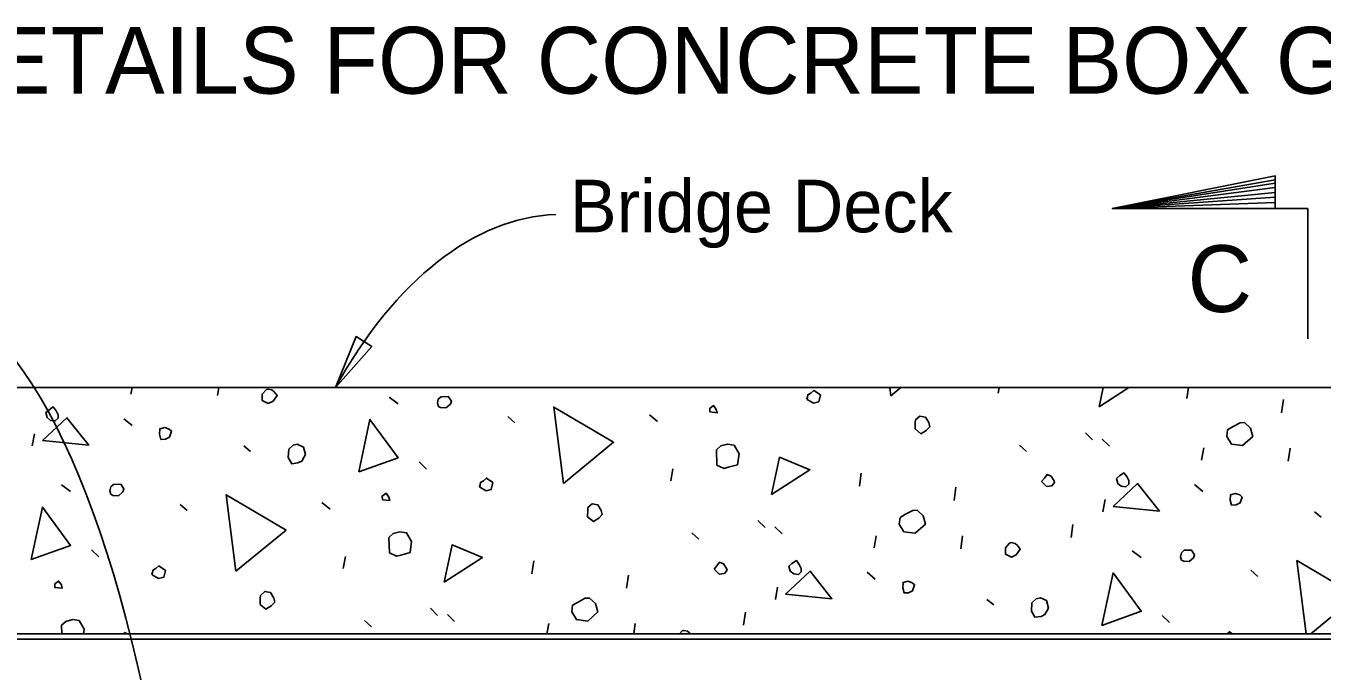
# Model space of a CAD drawing. Extents: x 112544 to 112597.1, y 111084 to 111107.1.
# Drawn here: x 112548.485 to 112552.213, y 111093.624 to 111095.48 of the extents above; entities that cross this region are included whole.
import ezdxf

# ---------------------------------------------------------------- set-up
doc = ezdxf.new("R2010")
doc.units = 0
for name, color, linetype in [('Dimension', 7, 'Continuous'), ('Miscellaneous', 7, 'Continuous'), ('SupstrConc', 7, 'Continuous'), ('TextStructures', 7, 'Continuous')]:
    doc.layers.add(name, color=color, linetype=linetype)

msp = doc.modelspace()

# ---------------------------------------------------------------- linework, layer by layer
at = {"layer": 'Dimension'}
for p, q in [((112551.609, 111094.9545), (112552.0777, 111095.037)), ((112552.0777, 111095.027), (112551.609, 111094.9545)), ((112551.609, 111094.9545), (112552.0777, 111095.0145)), ((112552.0777, 111095.0008), (112551.609, 111094.9545)), ((112551.609, 111094.9545), (112552.0777, 111094.987)), ((112552.0777, 111094.972), (112551.609, 111094.9545))]:
    msp.add_line(p, q, dxfattribs=at)
msp.add_lwpolyline([(112552.1714, 111094.5795), (112552.1714, 111094.9545), (112551.609, 111094.9545), (112552.0777, 111095.0483), (112552.0777, 111094.9545)], dxfattribs=at)
msp.add_lwpolyline([(112549.3749, 111094.4391), (112549.4796, 111094.558), (112549.4346, 111094.5859)], close=True, dxfattribs=at)
for centre, major_axis, ratio, start_param, end_param in [((112550.1201, 111092.5703), (0.1111, -2.3674), 0.464296, 3.141604, 3.781059), ((112548.1769, 111092.198), (0.0332, -2.5173), 0.313255, 2.075166, 3.141607)]:
    msp.add_ellipse(centre, major_axis=major_axis, ratio=ratio, start_param=start_param, end_param=end_param, dxfattribs=at)
at = {"layer": 'Miscellaneous'}
for p, q in [((112548.787, 111094.42), (112548.7903, 111094.4392)), ((112549.0363, 111094.4169), (112549.0395, 111094.4392)), ((112551.2812, 111094.4231), (112551.2839, 111094.4392)), ((112551.8236, 111094.408), (112551.8281, 111094.4392)), ((112549.5294, 111094.4118), (112549.5552, 111094.3929)), ((112552.0959, 111094.3671), (112552.1014, 111094.4048)), ((112548.7669, 111094.3499), (112548.7903, 111094.3303)), ((112549.8705, 111094.3557), (112549.8908, 111094.3379)), ((112550.278, 111094.3613), (112550.3013, 111094.3417)), ((112548.5032, 111094.2715), (112548.5093, 111094.3067)), ((112551.5317, 111094.3091), (112551.5527, 111094.2888)), ((112549.1115, 111094.2714), (112549.1312, 111094.2559)), ((112551.3419, 111094.2737), (112551.3622, 111094.2559)), ((112551.5805, 111094.2911), (112551.6015, 111094.2708)), ((112551.866, 111094.2304), (112551.872, 111094.2657)), ((112552.1153, 111094.2273), (112552.1207, 111094.265)), ((112549.6156, 111094.2253), (112549.6366, 111094.205)), ((112550.3394, 111094.1707), (112550.3455, 111094.206)), ((112550.8818, 111094.1556), (112550.8872, 111094.1933)), ((112548.5876, 111094.1595), (112548.6134, 111094.1405)), ((112551.8459, 111094.1603), (112551.8693, 111094.1407)), ((112551.1541, 111094.1147), (112551.1596, 111094.1524)), ((112551.5822, 111094.0819), (112551.5883, 111094.1172)), ((112548.9288, 111094.1034), (112548.9491, 111094.0855)), ((112549.3362, 111094.109), (112549.3596, 111094.0894)), ((112552.1905, 111094.0818), (112552.2101, 111094.0664)), ((112550.5899, 111094.0567), (112550.6109, 111094.0364)), ((112551.4907, 111094.0082), (112551.4961, 111094.0459)), ((112550.4001, 111094.0214), (112550.4204, 111094.0035)), ((112550.6387, 111094.0387), (112550.6597, 111094.0185)), ((112550.9242, 111093.978), (112550.9303, 111094.0133)), ((112551.1735, 111093.975), (112551.1789, 111094.0126)), ((112548.6738, 111093.9729), (112548.6948, 111093.9527)), ((112551.6666, 111093.9699), (112551.6924, 111093.9509)), ((112549.3976, 111093.9184), (112549.4037, 111093.9537)), ((112549.94, 111093.9033), (112549.9454, 111093.941)), ((112550.2124, 111093.8624), (112550.2178, 111093.9001)), ((112550.9041, 111093.908), (112550.9275, 111093.8883)), ((112552.0077, 111093.9138), (112552.028, 111093.8959)), ((112550.6404, 111093.8295), (112550.6465, 111093.8648)), ((112551.2487, 111093.8295), (112551.2684, 111093.814)), ((112549.6482, 111093.8044), (112549.6691, 111093.7841)), ((112549.697, 111093.7864), (112549.7179, 111093.7661)), ((112550.5489, 111093.7558), (112550.5543, 111093.7935)), ((112551.7528, 111093.7834), (112551.7738, 111093.7631)), ((112549.4583, 111093.769), (112549.4786, 111093.7512)), ((112549.9833, 111093.7309), (112549.9885, 111093.761)), ((112550.2329, 111093.7309), (112550.2371, 111093.7603)), ((112547.9235, 111093.7309), (112552.7436, 111093.7309)), ((112547.9277, 111093.7153), (112552.7436, 111093.7153))]:
    msp.add_line(p, q, dxfattribs=at)
for points in [[(112549.1648, 111094.4202), (112549.1645, 111094.402), (112549.1822, 111094.3939), (112549.196, 111094.4002), (112549.2073, 111094.4161), (112549.1992, 111094.4269), (112549.1925, 111094.4328), (112549.1815, 111094.4351), (112549.1767, 111094.4338), (112549.1648, 111094.4202)], [(112550.732, 111094.4054), (112550.7504, 111094.3948), (112550.7649, 111094.3986), (112550.77, 111094.4181), (112550.751, 111094.4312), (112550.7426, 111094.4237), (112550.7336, 111094.4187), (112550.732, 111094.4054), (112550.7307, 111094.4102)], [(112550.9726, 111094.4155), (112550.9696, 111094.4392)], [(112551.0014, 111094.4392), (112550.9726, 111094.4155)], [(112551.5711, 111094.3843), (112551.5829, 111094.4392)], [(112551.6564, 111094.4392), (112551.5711, 111094.3843)], [(112548.5461, 111094.3528), (112548.556, 111094.3451), (112548.5694, 111094.3435), (112548.5777, 111094.3509), (112548.5775, 111094.3612), (112548.5719, 111094.3727), (112548.5638, 111094.3835), (112548.5506, 111094.3747), (112548.5423, 111094.3673), (112548.5461, 111094.3528)], [(112549.6711, 111094.3851), (112549.6773, 111094.3816), (112549.693, 111094.3806), (112549.7056, 111094.3917), (112549.7085, 111094.4003), (112549.6998, 111094.4135), (112549.6792, 111094.4131), (112549.6708, 111094.4057), (112549.6685, 111094.3948), (112549.6711, 111094.3851)], [(112550.0308, 111094.1631), (112550.0029, 111094.3834), (112550.175, 111094.282), (112550.0308, 111094.1631)], [(112550.4519, 111094.3691), (112550.4731, 111094.3671), (112550.4705, 111094.3767), (112550.4625, 111094.3875), (112550.4517, 111094.3794), (112550.4519, 111094.3691)], [(112548.5327, 111094.2871), (112548.6032, 111094.3526), (112548.6657, 111094.2736), (112548.5327, 111094.2871)], [(112549.442, 111094.1969), (112549.4741, 111094.3478), (112549.5554, 111094.2376), (112549.442, 111094.1969)], [(112551.0424, 111094.3384), (112551.0421, 111094.3202), (112551.0587, 111094.3066), (112551.0743, 111094.3159), (112551.0845, 111094.3264), (112551.0812, 111094.3385), (112551.0719, 111094.3541), (112551.0555, 111094.3574), (112551.0429, 111094.3463), (112551.0424, 111094.3384)], [(112548.8696, 111094.3049), (112548.8735, 111094.2904), (112548.8862, 111094.2912), (112548.8976, 111094.2969), (112548.9034, 111094.314), (112548.8966, 111094.3199), (112548.885, 111094.3246), (112548.8705, 111094.3207), (112548.8696, 111094.3049)], [(112551.9382, 111094.2989), (112551.9519, 111094.2767), (112551.9841, 111094.2724), (112552.0134, 111094.2984), (112552.0069, 111094.3225), (112551.9897, 111094.3386), (112551.9769, 111094.3378), (112551.9565, 111094.3271), (112551.9409, 111094.3178), (112551.9382, 111094.2989)], [(112549.2408, 111094.262), (112549.2394, 111094.2384), (112549.2494, 111094.2203), (112549.267, 111094.2224), (112549.2784, 111094.2281), (112549.289, 111094.2465), (112549.2832, 111094.2682), (112549.2654, 111094.2764), (112549.2534, 111094.2732), (112549.2408, 111094.262)], [(112550.4707, 111094.2603), (112550.472, 111094.2166), (112550.4928, 111094.2067), (112550.5049, 111094.2099), (112550.5314, 111094.217), (112550.5358, 111094.2492), (112550.5214, 111094.2739), (112550.5025, 111094.2766), (112550.4832, 111094.2714), (112550.4707, 111094.2603)], [(112550.6293, 111094.132), (112550.6524, 111094.2391), (112550.7397, 111094.203), (112550.6293, 111094.132)], [(112551.6251, 111094.1633), (112551.635, 111094.1556), (112551.6483, 111094.154), (112551.6567, 111094.1614), (112551.6565, 111094.1717), (112551.6509, 111094.1831), (112551.6428, 111094.1939), (112551.6296, 111094.1852), (112551.6212, 111094.1778), (112551.6251, 111094.1633)], [(112548.7294, 111094.1327), (112548.7355, 111094.1292), (112548.7513, 111094.1283), (112548.7638, 111094.1394), (112548.7667, 111094.1479), (112548.758, 111094.1611), (112548.7374, 111094.1608), (112548.729, 111094.1534), (112548.7268, 111094.1424), (112548.7294, 111094.1327)], [(112549.7903, 111094.153), (112549.8086, 111094.1424), (112549.8231, 111094.1463), (112549.8282, 111094.1658), (112549.8092, 111094.1788), (112549.8009, 111094.1714), (112549.7919, 111094.1664), (112549.7903, 111094.153), (112549.789, 111094.1579)], [(112551.4061, 111094.1693), (112551.4203, 111094.155), (112551.4354, 111094.1564), (112551.4431, 111094.1663), (112551.4419, 111094.1711), (112551.4331, 111094.1843), (112551.4215, 111094.189), (112551.4138, 111094.1791), (112551.4061, 111094.1693)], [(112551.6117, 111094.0976), (112551.6821, 111094.163), (112551.7447, 111094.084), (112551.6117, 111094.0976)], [(112549.0891, 111093.9108), (112549.0611, 111094.1311), (112549.2332, 111094.0296), (112549.0891, 111093.9108)], [(112549.5101, 111094.1168), (112549.5314, 111094.1147), (112549.5288, 111094.1244), (112549.5207, 111094.1351), (112549.5099, 111094.1271), (112549.5101, 111094.1168)], [(112551.9485, 111094.1153), (112551.9524, 111094.1009), (112551.9652, 111094.1017), (112551.9766, 111094.1073), (112551.9824, 111094.1244), (112551.9756, 111094.1304), (112551.964, 111094.135), (112551.9495, 111094.1311), (112551.9485, 111094.1153)], [(112548.5003, 111093.9445), (112548.5323, 111094.0955), (112548.6136, 111093.9853), (112548.5003, 111093.9445)], [(112550.1007, 111094.0861), (112550.1004, 111094.0679), (112550.117, 111094.0542), (112550.1326, 111094.0636), (112550.1427, 111094.0741), (112550.1395, 111094.0861), (112550.1301, 111094.1017), (112550.1137, 111094.1051), (112550.1011, 111094.094), (112550.1007, 111094.0861)], [(112550.9964, 111094.0466), (112551.0101, 111094.0244), (112551.0423, 111094.0201), (112551.0716, 111094.046), (112551.0651, 111094.0702), (112551.0479, 111094.0862), (112551.0352, 111094.0854), (112551.0147, 111094.0748), (112550.9991, 111094.0654), (112550.9964, 111094.0466)], [(112549.5289, 111094.0079), (112549.5302, 111093.9643), (112549.551, 111093.9543), (112549.5631, 111093.9576), (112549.5897, 111093.9647), (112549.594, 111093.9969), (112549.5796, 111094.0215), (112549.5608, 111094.0242), (112549.5415, 111094.0191), (112549.5289, 111094.0079)], [(112549.6875, 111093.8796), (112549.7106, 111093.9867), (112549.7979, 111093.9506), (112549.6875, 111093.8796)], [(112551.302, 111093.9783), (112551.3017, 111093.9601), (112551.3194, 111093.9519), (112551.3332, 111093.9582), (112551.3445, 111093.9742), (112551.3364, 111093.985), (112551.3297, 111093.9909), (112551.3187, 111093.9932), (112551.3139, 111093.9919), (112551.302, 111093.9783)], [(112551.8083, 111093.9432), (112551.8145, 111093.9397), (112551.8302, 111093.9387), (112551.8428, 111093.9498), (112551.8457, 111093.9584), (112551.837, 111093.9716), (112551.8163, 111093.9712), (112551.808, 111093.9638), (112551.8057, 111093.9528), (112551.8083, 111093.9432)], [(112550.4643, 111093.9169), (112550.4785, 111093.9026), (112550.4937, 111093.9041), (112550.5014, 111093.9139), (112550.5001, 111093.9188), (112550.4914, 111093.9319), (112550.4798, 111093.9366), (112550.472, 111093.9268), (112550.4643, 111093.9169)], [(112550.6833, 111093.9109), (112550.6932, 111093.9032), (112550.7065, 111093.9016), (112550.7149, 111093.909), (112550.7147, 111093.9193), (112550.7091, 111093.9308), (112550.701, 111093.9415), (112550.6878, 111093.9328), (112550.6795, 111093.9254), (112550.6833, 111093.9109)], [(112552.1668, 111093.7309), (112552.1401, 111093.9415), (112552.3122, 111093.8401), (112552.1798, 111093.7309)], [(112548.8485, 111093.9007), (112548.8668, 111093.8901), (112548.8813, 111093.8939), (112548.8865, 111093.9134), (112548.8675, 111093.9265), (112548.8591, 111093.919), (112548.8501, 111093.914), (112548.8485, 111093.9007), (112548.8472, 111093.9055)], [(112550.6699, 111093.8452), (112550.7404, 111093.9107), (112550.8029, 111093.8317), (112550.6699, 111093.8452)], [(112551.5792, 111093.755), (112551.6113, 111093.9059), (112551.6926, 111093.7957), (112551.5792, 111093.755)], [(112548.5683, 111093.8644), (112548.5896, 111093.8624), (112548.587, 111093.872), (112548.5789, 111093.8828), (112548.5681, 111093.8747), (112548.5683, 111093.8644)], [(112551.0068, 111093.863), (112551.0107, 111093.8485), (112551.0234, 111093.8493), (112551.0348, 111093.855), (112551.0406, 111093.8721), (112551.0338, 111093.878), (112551.0222, 111093.8827), (112551.0077, 111093.8788), (112551.0068, 111093.863)], [(112549.1589, 111093.8337), (112549.1586, 111093.8155), (112549.1752, 111093.8019), (112549.1908, 111093.8112), (112549.2009, 111093.8217), (112549.1977, 111093.8338), (112549.1883, 111093.8494), (112549.1719, 111093.8527), (112549.1594, 111093.8416), (112549.1589, 111093.8337)], [(112550.0546, 111093.7942), (112550.0683, 111093.772), (112550.1006, 111093.7677), (112550.1298, 111093.7937), (112550.1234, 111093.8178), (112550.1061, 111093.8339), (112550.0934, 111093.8331), (112550.073, 111093.8224), (112550.0573, 111093.8131), (112550.0546, 111093.7942)], [(112551.378, 111093.8201), (112551.3766, 111093.7964), (112551.3866, 111093.7784), (112551.4042, 111093.7805), (112551.4156, 111093.7862), (112551.4262, 111093.8046), (112551.4204, 111093.8263), (112551.4026, 111093.8345), (112551.3906, 111093.8312), (112551.378, 111093.8201)], [(112548.6504, 111093.7309), (112548.6522, 111093.7446), (112548.6378, 111093.7692), (112548.619, 111093.7719), (112548.5997, 111093.7667), (112548.5871, 111093.7556)], [(112548.5871, 111093.7556), (112548.5879, 111093.7309)], [(112548.768, 111093.7309), (112548.7688, 111093.7344), (112548.7773, 111093.7309)], [(112550.396, 111093.7309), (112550.3947, 111093.7326), (112550.3879, 111093.7386), (112550.3769, 111093.7408), (112550.3721, 111093.7395), (112550.3645, 111093.7309)], [(112551.9552, 111093.7309), (112551.9464, 111093.7369), (112551.9396, 111093.7309)]]:
    msp.add_lwpolyline(points, dxfattribs=at)
at = {"layer": 'SupstrConc'}
msp.add_line((112544.2555, 111094.4392), (112552.7436, 111094.4392), dxfattribs=at)

# ---------------------------------------------------------------- texts
at = {"layer": 'TextStructures'}
for s, height, p in [('LIGHTING DETAILS FOR CONCRETE BOX GIRDER BRIDGE', 0.192, (112546.9154, 111095.285)), ('Bridge Deck', 0.1512, (112550.049, 111094.8861)), ('C', 0.192, (112551.8257, 111094.6568))]:
    msp.add_text(s, height=height, dxfattribs=at).set_placement(p)

doc.saveas('drawing.dxf')
